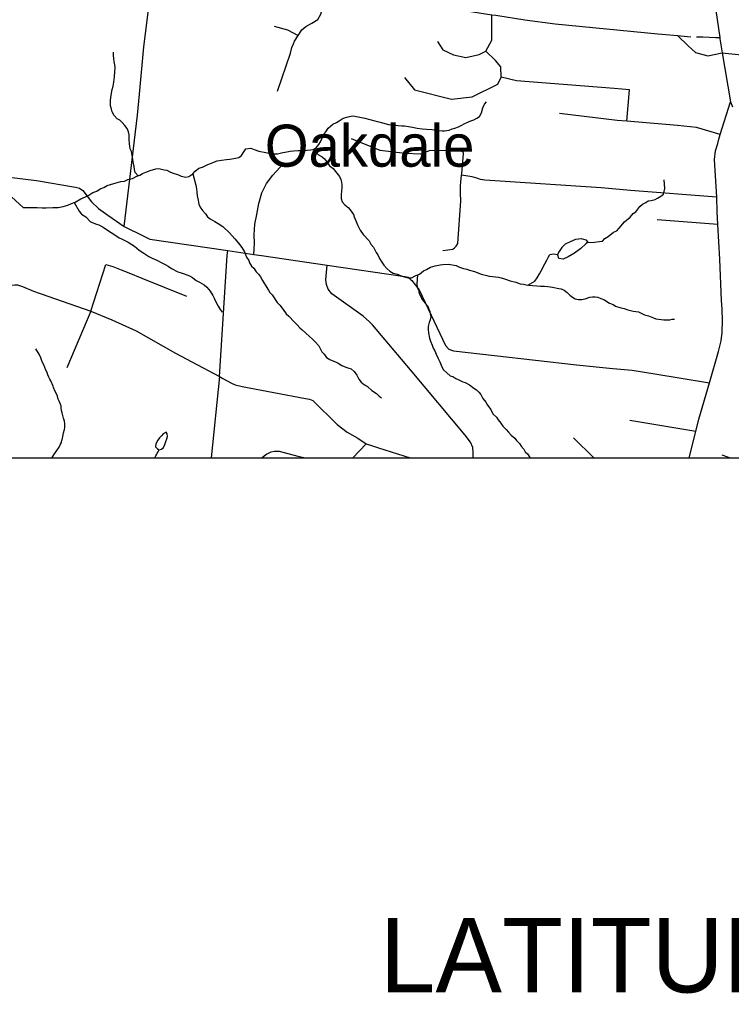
# Model space of a CAD drawing. Extents: x 0 to 34, y 0 to 22.
# Drawn here: x 2.395 to 3.731, y 13.194 to 15.023 of the extents above; entities that cross this region are included whole.
import ezdxf

# ---------------------------------------------------------------- set-up
doc = ezdxf.new("R2010")
doc.units = 0
for name, color, linetype in [('GM_X_County_Road', 7, 'Continuous'), ('GM_X_County_ROW', 7, 'Continuous'), ('GM_X_Minor_Lake', 7, 'Continuous'), ('GM_X_Minor_River', 7, 'Continuous'), ('GM_X_Township_Subdivision', 7, 'Continuous'), ('GM_X_Unincorporated_Text', 7, 'Continuous'), ('SH_Data', 7, 'Continuous')]:
    doc.layers.add(name, color=color, linetype=linetype)

msp = doc.modelspace()

# ---------------------------------------------------------------- linework, layer by layer
at = {"layer": 'GM_X_County_Road'}
for points in [[(2.2258, 15.2235), (2.2987, 15.186), (2.3184, 15.1766), (2.3423, 15.1693), (2.373, 15.1638), (2.4076, 15.1648), (2.4442, 15.1636), (2.6483, 15.131), (2.7856, 15.1056), (2.9731, 15.0809), (3.1585, 15.0511), (3.281, 15.0319), (3.2884, 15.0308), (3.343, 15.0226), (3.3998, 15.0151), (3.5922, 14.9963), (3.5999, 14.9956)], [(2.6198, 14.8825), (2.6281, 14.9717), (2.6483, 15.131)], [(3.6945, 15.0867), (3.7086, 14.9889), (3.7089, 14.9865), (3.7134, 14.9601), (3.7288, 14.8681), (3.7325, 14.8589)], [(3.5999, 14.9956), (3.6295, 14.9929), (3.6491, 14.9734), (3.6629, 14.9607), (3.686, 14.9547), (3.7134, 14.9601)], [(3.6295, 14.9929), (3.6543, 14.9903)], [(3.6768, 14.9901), (3.7006, 14.9892)], [(3.7134, 14.9601), (3.8399, 14.9472), (3.85, 14.9435), (3.9106, 14.9291), (3.9265, 14.9232), (3.9472, 14.9185), (4.0106, 14.9118), (4.0583, 14.9068)], [(3.7129, 14.4789), (3.7118, 14.495), (3.7085, 14.5729), (3.7053, 14.6379), (3.7039, 14.6616), (3.7029, 14.6892), (3.699, 14.7598), (3.7006, 14.7761), (3.7047, 14.7898), (3.7068, 14.7981), (3.7092, 14.807), (3.7288, 14.8681)], [(2.3393, 14.7315), (2.4266, 14.7207), (2.4996, 14.7079), (2.5073, 14.7062), (2.5134, 14.7016), (2.5301, 14.6807), (2.5431, 14.6681), (2.5604, 14.6558), (2.5911, 14.634), (2.6279, 14.6158), (2.6392, 14.6102), (2.7855, 14.589), (2.8343, 14.5818), (2.8491, 14.5796)], [(2.7703, 14.3525), (2.7846, 14.5795), (2.7846, 14.5795)], [(2.7846, 14.5795), (2.7855, 14.589)], [(2.8491, 14.5796), (2.9723, 14.5615), (3.1178, 14.5405), (3.1238, 14.5388), (3.129, 14.5343)], [(2, 14.5396), (2.019, 14.5376), (2.0727, 14.5308), (2.2375, 14.5181), (2.273, 14.5212), (2.3066, 14.52), (2.3558, 14.5219), (2.3858, 14.5244), (2.3884, 14.5247), (2.3912, 14.5244), (2.4003, 14.5218), (2.4213, 14.5128), (2.5283, 14.475), (2.5681, 14.4589), (2.6134, 14.4384), (2.6877, 14.3965), (2.7703, 14.3525)], [(3.129, 14.5343), (3.1309, 14.5326), (3.1449, 14.5152), (3.1617, 14.4795), (3.1943, 14.4106), (3.2005, 14.404), (3.2088, 14.4008), (3.4396, 14.3745), (3.5082, 14.3678), (3.5441, 14.3643), (3.5868, 14.3576), (3.6892, 14.3408)], [(3.6512, 14.2), (3.6635, 14.249), (3.6693, 14.2725), (3.6892, 14.3408), (3.7063, 14.3997), (3.7111, 14.4197), (3.7131, 14.4349), (3.714, 14.4585), (3.7129, 14.4777), (3.7129, 14.4789)], [(2.7703, 14.3525), (2.7763, 14.3485), (2.7925, 14.34), (2.7996, 14.3369), (2.8125, 14.3338), (2.9315, 14.3114), (2.9387, 14.3101), (2.9454, 14.3072), (2.9907, 14.2625), (3.0097, 14.2478), (3.0297, 14.2365), (3.0449, 14.2264), (3.0549, 14.2233), (3.0685, 14.2188), (3.1275, 14.2)]]:
    msp.add_lwpolyline(points, dxfattribs=at)
at = {"layer": 'GM_X_County_ROW'}
for points in [[(3.6649, 14.9905), (3.6768, 14.9901)], [(3.7006, 14.9892), (3.7086, 14.9889)], [(2.5911, 14.634), (2.6162, 14.8432), (2.6198, 14.8825)]]:
    msp.add_lwpolyline(points, dxfattribs=at)
at = {"layer": 'GM_X_Minor_Lake'}
for points in [[(2.657, 14.2147), (2.6612, 14.2158), (2.665, 14.2195), (2.6674, 14.2248), (2.6691, 14.2308), (2.6711, 14.2357), (2.6723, 14.2402), (2.6717, 14.2448), (2.6702, 14.2483), (2.6641, 14.245), (2.661, 14.2412), (2.6575, 14.2371), (2.6543, 14.233), (2.6508, 14.2259), (2.6499, 14.2206)], [(2.6499, 14.2206), (2.6538, 14.2165), (2.657, 14.2147)]]:
    msp.add_lwpolyline(points, dxfattribs=at)
at = {"layer": 'GM_X_Minor_River'}
for points in [[(2.6176, 14.7296), (2.6118, 14.7354), (2.6108, 14.7411), (2.6098, 14.7472), (2.6088, 14.7526), (2.6075, 14.7598), (2.6062, 14.7679), (2.6049, 14.7751), (2.6027, 14.7802), (2.6017, 14.7848), (2.6011, 14.7897), (2.6006, 14.7981), (2.6004, 14.8065), (2.5994, 14.8119), (2.5965, 14.8184), (2.5925, 14.8239), (2.5873, 14.8297), (2.5829, 14.8336), (2.578, 14.8361), (2.5721, 14.8427), (2.5685, 14.8493), (2.5671, 14.8546), (2.5657, 14.8608), (2.5655, 14.8654), (2.5653, 14.8707), (2.5662, 14.8764), (2.5675, 14.8843), (2.5689, 14.8915), (2.5705, 14.8976), (2.5719, 14.9055), (2.5733, 14.915), (2.5739, 14.9245), (2.5741, 14.9321), (2.5735, 14.9375), (2.5722, 14.944), (2.5716, 14.9493), (2.5714, 14.9562), (2.5711, 14.9615)], [(3.1411, 14.8188), (3.1502, 14.8178), (3.1586, 14.8168), (3.1681, 14.8161), (3.173, 14.8156), (3.1821, 14.8142), (3.1878, 14.8137), (3.1923, 14.8139), (3.2007, 14.8152), (3.2065, 14.8174), (3.2115, 14.8187), (3.2184, 14.8216), (3.2246, 14.8245), (3.2292, 14.827), (3.2369, 14.831), (3.2415, 14.8324), (3.2469, 14.8345), (3.2527, 14.8374), (3.2577, 14.8407), (3.2617, 14.8474), (3.2642, 14.8572), (3.2675, 14.864), (3.271, 14.8685)], [(2.3576, 14.7092), (2.4016, 14.6696), (2.4138, 14.6697), (2.4218, 14.6702), (2.4279, 14.67), (2.437, 14.6694), (2.4446, 14.6692), (2.4571, 14.6696), (2.4674, 14.6701), (2.4766, 14.6721), (2.4854, 14.6741), (2.4923, 14.6774), (2.4989, 14.6799), (2.5097, 14.6864), (2.5185, 14.69), (2.5247, 14.6929), (2.5324, 14.698), (2.5397, 14.7004), (2.5463, 14.7052), (2.5532, 14.7077), (2.5594, 14.7113), (2.5652, 14.7134), (2.5763, 14.7162), (2.5851, 14.7186), (2.5916, 14.7192), (2.5981, 14.7224), (2.6065, 14.7245), (2.6147, 14.7288), (2.6208, 14.7305), (2.6254, 14.7338), (2.635, 14.7374), (2.64, 14.7391), (2.6504, 14.7423), (2.6561, 14.7429), (2.6663, 14.7407), (2.6712, 14.7398), (2.6769, 14.737), (2.6814, 14.7353), (2.6934, 14.7312), (2.6979, 14.7288), (2.707, 14.7266), (2.7124, 14.7283), (2.7201, 14.7331), (2.7244, 14.7383), (2.7314, 14.7438), (2.7379, 14.7459), (2.7483, 14.7506), (2.7549, 14.7534), (2.7606, 14.7556), (2.7656, 14.7573), (2.774, 14.7586), (2.7832, 14.7599), (2.7893, 14.7605), (2.797, 14.7622), (2.8061, 14.7638), (2.8112, 14.7675), (2.8155, 14.7742), (2.8195, 14.7798), (2.829, 14.7814), (2.8351, 14.779), (2.8437, 14.7757), (2.857, 14.773), (2.863, 14.7717), (2.8694, 14.7708), (2.8786, 14.7709), (2.8889, 14.7729), (2.8965, 14.7742), (2.9023, 14.776), (2.9088, 14.7766), (2.9179, 14.7771), (2.9285, 14.7768), (2.9343, 14.7774), (2.9408, 14.7779), (2.9457, 14.7786), (2.9515, 14.7818), (2.9566, 14.7882), (2.9594, 14.7934), (2.9622, 14.799), (2.9655, 14.8073), (2.9694, 14.8118), (2.9738, 14.8189), (2.9824, 14.8263), (2.9897, 14.8295), (2.9947, 14.8328), (3.0021, 14.8379), (3.0117, 14.8403), (3.0189, 14.842), (3.0239, 14.8415), (3.0333, 14.8397), (3.0424, 14.8379), (3.0522, 14.835), (3.0616, 14.8328), (3.0662, 14.8316), (3.076, 14.8286), (3.0869, 14.8256), (3.0964, 14.825), (3.1055, 14.824), (3.1124, 14.8234), (3.1173, 14.8233), (3.132, 14.8206), (3.1411, 14.8188)], [(2.946, 14.7767), (2.9505, 14.7739), (2.9557, 14.7691), (2.9624, 14.7648), (2.9669, 14.7616), (2.9706, 14.7562), (2.9764, 14.748), (2.9835, 14.7432), (2.9879, 14.7374), (2.9953, 14.7281), (2.9978, 14.7227), (2.9992, 14.7173), (2.9994, 14.7127), (2.9993, 14.7066), (2.9988, 14.7021), (2.9982, 14.6929), (2.998, 14.6869), (3.0001, 14.6807), (3.0049, 14.6749), (3.0112, 14.6701), (3.0149, 14.6654), (3.0215, 14.6569), (3.0225, 14.6523), (3.0265, 14.6434), (3.029, 14.6373), (3.0337, 14.6276), (3.0395, 14.6191), (3.0506, 14.6073), (3.0542, 14.6011), (3.059, 14.5953), (3.0616, 14.5907), (3.0641, 14.5856), (3.067, 14.581), (3.0702, 14.5744), (3.0731, 14.569), (3.0783, 14.5616), (3.0838, 14.5554), (3.0898, 14.5506), (3.0961, 14.5467), (3.1037, 14.5445), (3.1123, 14.5409), (3.124, 14.5379), (3.1305, 14.5381), (3.1386, 14.5424), (3.1451, 14.5445), (3.1525, 14.5512), (3.1587, 14.5533), (3.166, 14.558), (3.1748, 14.5601), (3.184, 14.5621), (3.1893, 14.5627), (3.1996, 14.5632), (3.214, 14.5609), (3.2204, 14.558), (3.2279, 14.5552), (3.2343, 14.5538), (3.2389, 14.5522), (3.2483, 14.5496), (3.2532, 14.5476), (3.2607, 14.5447), (3.2717, 14.5425), (3.2762, 14.5412), (3.2823, 14.5403), (3.2933, 14.5389), (3.2982, 14.538), (3.3069, 14.5354), (3.3152, 14.5325), (3.3261, 14.53), (3.3344, 14.5267), (3.3401, 14.5261), (3.3454, 14.5245), (3.3499, 14.524), (3.3575, 14.5234), (3.3651, 14.5228), (3.3723, 14.5222), (3.3799, 14.5224), (3.386, 14.5218), (3.3905, 14.5209), (3.3951, 14.5204), (3.4064, 14.5178), (3.4113, 14.5169), (3.417, 14.5145), (3.4222, 14.5101), (3.4274, 14.5054), (3.4322, 14.5015), (3.4374, 14.4983), (3.4435, 14.4974), (3.4496, 14.4972), (3.4561, 14.4985), (3.4649, 14.5017), (3.4699, 14.5023), (3.4748, 14.5022), (3.4801, 14.5013), (3.4854, 14.4989), (3.4922, 14.4964), (3.4966, 14.4936), (3.5015, 14.4904), (3.5086, 14.4875), (3.5131, 14.4848), (3.5214, 14.4819), (3.5294, 14.4801)], [(2.72, 14.733), (2.7256, 14.7116), (2.7266, 14.7047), (2.7272, 14.6986), (2.7281, 14.6917), (2.7302, 14.6837), (2.7315, 14.6764), (2.7336, 14.6703), (2.7384, 14.664), (2.7439, 14.6578), (2.7472, 14.6524), (2.7528, 14.6488), (2.761, 14.6436), (2.7674, 14.6396), (2.776, 14.634), (2.789, 14.6223), (2.7938, 14.6168), (2.7989, 14.6109), (2.8059, 14.6027), (2.8118, 14.595), (2.8169, 14.5864), (2.8205, 14.5768), (2.8248, 14.5706), (2.8266, 14.566), (2.8299, 14.5598), (2.8343, 14.5563), (2.8387, 14.5489), (2.8432, 14.545), (2.8468, 14.5395), (2.8508, 14.533), (2.8545, 14.5264), (2.8617, 14.5147), (2.8643, 14.5101), (2.8691, 14.5058), (2.8779, 14.4918), (2.8834, 14.4863), (2.8897, 14.4786), (2.8952, 14.4704), (2.9004, 14.4661), (2.91, 14.4551), (2.9155, 14.4497), (2.9207, 14.4442), (2.9251, 14.4399), (2.9385, 14.4281), (2.9452, 14.4218), (2.9496, 14.4175), (2.9563, 14.4101), (2.9621, 14.3989), (2.9661, 14.3942), (2.9705, 14.3883), (2.9773, 14.3844), (2.9825, 14.3819), (2.9878, 14.3799), (2.9927, 14.3774), (2.9994, 14.3731), (3.0069, 14.3698), (3.0126, 14.3681), (3.0171, 14.3669), (3.0227, 14.3618), (3.0278, 14.3548), (3.0314, 14.3474), (3.0358, 14.342), (3.0418, 14.3372), (3.0478, 14.3336), (3.0559, 14.3262), (3.0645, 14.3206), (3.0697, 14.3159), (3.0742, 14.3127)], [(3.4608, 14.6044), (3.4733, 14.6045), (3.4832, 14.6059), (3.4887, 14.6069), (3.493, 14.6117), (3.4992, 14.6154), (3.5093, 14.6238), (3.5154, 14.6263), (3.5201, 14.6308), (3.5296, 14.6431), (3.5405, 14.6519), (3.546, 14.6586), (3.551, 14.6615), (3.5589, 14.672), (3.5639, 14.676), (3.5697, 14.6793), (3.5744, 14.6822), (3.5801, 14.6832), (3.5874, 14.6852), (3.592, 14.6874), (3.5982, 14.6914), (3.6029, 14.6951), (3.6054, 14.7057), (3.6044, 14.7221)], [(2.4976, 14.6794), (2.5068, 14.6629), (2.5112, 14.6571), (2.519, 14.6523), (2.5279, 14.6433), (2.5392, 14.6384), (2.5437, 14.6371), (2.552, 14.6327), (2.562, 14.6259), (2.5718, 14.6196), (2.5815, 14.6128), (2.586, 14.6112), (2.5987, 14.6047), (2.6055, 14.6007), (2.6103, 14.5975), (2.6193, 14.5901), (2.6278, 14.5841), (2.6376, 14.5777), (2.6436, 14.5745), (2.6522, 14.5712), (2.662, 14.566), (2.6691, 14.562), (2.6736, 14.5596), (2.6799, 14.5556), (2.6919, 14.5492), (2.6965, 14.5479), (2.7036, 14.5451), (2.7138, 14.5413), (2.7194, 14.5385), (2.7261, 14.5326), (2.7325, 14.5294), (2.7411, 14.5246), (2.7463, 14.5203), (2.7522, 14.5125), (2.7573, 14.5047), (2.7605, 14.4985), (2.763, 14.4928), (2.7678, 14.4846), (2.7714, 14.4781), (2.7749, 14.4732)], [(3.4125, 14.5946), (3.4195, 14.6015), (3.4283, 14.6063), (3.4383, 14.6106), (3.4485, 14.6119), (3.4572, 14.6094), (3.4609, 14.6048), (3.4574, 14.6014), (3.4481, 14.5929), (3.4362, 14.5844), (3.4242, 14.5771), (3.415, 14.5731), (3.4067, 14.5741), (3.4046, 14.5806), (3.4044, 14.5819)], [(3.3486, 14.5241), (3.3615, 14.5313), (3.3659, 14.5376), (3.3706, 14.5451), (3.3738, 14.5507), (3.3803, 14.5642), (3.3843, 14.571), (3.3871, 14.577), (3.3899, 14.5819), (3.3976, 14.5826), (3.4044, 14.5816)], [(3.4125, 14.5946), (3.4071, 14.5873), (3.4044, 14.5819)], [(3.1416, 14.5434), (3.1404, 14.5268), (3.141, 14.5199), (3.1432, 14.5153), (3.1449, 14.5087), (3.1478, 14.503), (3.1499, 14.4979), (3.1562, 14.4905), (3.1606, 14.4847), (3.1627, 14.4793), (3.1645, 14.4747), (3.1655, 14.4701), (3.1665, 14.4647), (3.1652, 14.4587), (3.1636, 14.4542), (3.1618, 14.4462), (3.1613, 14.4409), (3.1619, 14.4344), (3.1639, 14.4244), (3.1657, 14.4187), (3.1693, 14.4114), (3.171, 14.4056), (3.1743, 14.4009), (3.1768, 14.3944), (3.18, 14.3863), (3.1836, 14.3801), (3.1872, 14.3709), (3.1905, 14.3651), (3.1964, 14.3596), (3.2027, 14.3537), (3.2076, 14.3524), (3.2132, 14.3488), (3.2177, 14.3472), (3.2264, 14.3427), (3.2309, 14.3415), (3.2391, 14.3371), (3.2473, 14.3304), (3.2522, 14.3276), (3.2566, 14.3232), (3.2603, 14.3186), (3.2639, 14.3112), (3.2698, 14.3042), (3.2727, 14.2988), (3.2789, 14.2903), (3.2829, 14.2825), (3.2896, 14.2763), (3.2929, 14.2712), (3.298, 14.265), (3.3017, 14.2595), (3.308, 14.2533), (3.3124, 14.2478), (3.3172, 14.2427), (3.3239, 14.2368), (3.3272, 14.2322), (3.3331, 14.2267), (3.3357, 14.222), (3.3408, 14.2162), (3.3437, 14.2112), (3.3482, 14.2072), (3.3522, 14.2003), (3.3525, 14.2)], [(3.5294, 14.4801), (3.5361, 14.4776), (3.546, 14.4755), (3.5562, 14.4737), (3.5675, 14.4684), (3.575, 14.4667), (3.5844, 14.463), (3.5889, 14.4609), (3.5935, 14.46), (3.5988, 14.4595), (3.6037, 14.459), (3.609, 14.4589), (3.6147, 14.4591), (3.6193, 14.4605), (3.6238, 14.4601)], [(2.4557, 14.2), (2.4558, 14.2002), (2.4606, 14.2073), (2.465, 14.2136), (2.4689, 14.22), (2.4717, 14.2256), (2.4733, 14.2286), (2.4734, 14.2309), (2.4746, 14.2339), (2.4759, 14.2396), (2.4773, 14.2468), (2.4789, 14.2528), (2.4798, 14.2566), (2.48, 14.2635), (2.479, 14.2688), (2.4772, 14.2746), (2.4759, 14.2796), (2.4748, 14.2842), (2.4738, 14.2884), (2.4732, 14.2937), (2.4729, 14.2968), (2.4708, 14.3018), (2.4693, 14.306), (2.4676, 14.3103), (2.4658, 14.3156), (2.464, 14.3199), (2.4619, 14.3241), (2.4586, 14.3318), (2.4579, 14.3341), (2.4533, 14.3442), (2.4515, 14.3476), (2.45, 14.3511), (2.4479, 14.3557), (2.4465, 14.36), (2.4443, 14.3642), (2.4425, 14.3692), (2.4404, 14.3742), (2.4382, 14.3788), (2.4361, 14.3839), (2.4347, 14.3873), (2.4314, 14.3943), (2.4296, 14.3977), (2.4274, 14.4012), (2.4256, 14.4047)], [(2.6489, 14.2), (2.6506, 14.2035), (2.6522, 14.2065), (2.6531, 14.2087), (2.655, 14.2114), (2.657, 14.2147)]]:
    msp.add_lwpolyline(points, dxfattribs=at)
at = {"layer": 'GM_X_Township_Subdivision'}
for points in [[(2.8788, 14.8884), (2.903, 14.9595), (2.906, 14.9705), (2.9086, 14.9773), (2.9106, 14.9824), (2.9175, 14.9927), (2.9243, 15.0038), (2.9323, 15.0098), (2.9433, 15.0159), (2.9542, 15.0232), (2.96, 15.0328), (2.9638, 15.0458), (2.9731, 15.0809)], [(3.1791, 14.9817), (3.1891, 14.9662), (3.2089, 14.9569), (3.2321, 14.9514), (3.2569, 14.9574), (3.2696, 14.9635), (3.2812, 14.9844), (3.2812, 15.0159), (3.281, 15.0319)], [(2.8724, 15.0102), (2.8973, 15.0035), (2.9175, 14.9927)], [(3.1174, 14.9138), (3.1361, 14.8907), (3.2056, 14.8736), (3.2442, 14.878), (3.2922, 14.9017), (3.2983, 14.9149), (3.2977, 14.9343), (3.2878, 14.9458), (3.2696, 14.9635)], [(3.5104, 14.8933), (3.3275, 14.9078), (3.2983, 14.9149)], [(3.5395, 14.891), (3.5104, 14.8933)], [(3.534, 14.8318), (3.5395, 14.891)], [(3.7092, 14.807), (3.6647, 14.8203), (3.6296, 14.8239), (3.534, 14.8318), (3.5161, 14.8334), (3.4079, 14.8466)], [(3.2244, 14.733), (3.228, 14.7716), (3.2278, 14.7727), (3.2271, 14.7736), (3.225, 14.7749), (3.2209, 14.7761), (3.1654, 14.777), (3.1471, 14.7699), (3.1179, 14.771), (3.0716, 14.7771), (3.0175, 14.7986)], [(2.8343, 14.5818), (2.8356, 14.603), (2.8348, 14.6186), (2.8364, 14.6383), (2.8403, 14.6568), (2.8439, 14.6776), (2.8497, 14.6976), (2.8585, 14.7149), (2.8703, 14.7309), (2.8902, 14.7524)], [(3.1888, 14.5889), (3.2075, 14.5915), (3.211, 14.594), (3.2141, 14.5974), (3.2169, 14.6022), (3.2227, 14.6826), (3.2219, 14.6967), (3.2223, 14.7111), (3.2229, 14.7176), (3.2241, 14.7304), (3.2244, 14.733)], [(3.2639, 14.7218), (3.2635, 14.7219), (3.2594, 14.7223), (3.253, 14.7252), (3.2439, 14.7277), (3.2241, 14.7304)], [(3.7029, 14.6892), (3.5414, 14.7019), (3.4859, 14.707), (3.2677, 14.7214), (3.2639, 14.7218)], [(3.7053, 14.6379), (3.5914, 14.6467)], [(2.5283, 14.475), (2.5569, 14.5629), (2.5701, 14.5592), (2.5853, 14.5531), (2.6001, 14.5473), (2.6241, 14.5371), (2.7084, 14.5037)], [(3.2459, 14.2), (3.2461, 14.2096), (3.2452, 14.2195), (3.2409, 14.2291), (3.231, 14.2426), (3.1286, 14.3648), (3.0571, 14.4494), (3.0512, 14.4552), (3.0393, 14.4658), (2.9808, 14.5078), (2.9742, 14.5164), (2.971, 14.5252), (2.9697, 14.5339), (2.9723, 14.5615)], [(2.5283, 14.475), (2.4837, 14.3691)], [(2.7703, 14.3525), (2.7545, 14.2)], [(3.6635, 14.249), (3.5396, 14.27)], [(3.4723, 14.2), (3.4339, 14.2376)], [(3.0449, 14.2264), (3.0201, 14.2)], [(2.9282, 14.2), (2.9179, 14.2021), (2.8823, 14.2115), (2.8735, 14.2115), (2.8665, 14.2103), (2.8591, 14.2069), (2.8536, 14.2031), (2.8501, 14.2)], [(3.7266, 14.2), (3.7238, 14.2009), (3.713, 14.2047)]]:
    msp.add_lwpolyline(points, dxfattribs=at)
at = {"layer": 'SH_Data'}
msp.add_line((2, 14.2), (8.8, 14.2), dxfattribs=at)

# ---------------------------------------------------------------- texts
at = {"layer": 'GM_X_Unincorporated_Text'}
msp.add_text('Oakdale', height=0.07898, rotation=0, dxfattribs=at).set_placement((2.855, 14.7465))
at = {"layer": 'SH_Data'}
msp.add_text('LATITUDE:  39° 16\' 12"     LONGITUDE:  -84° 34\' 26"', height=0.14, dxfattribs=at).set_placement((3.071, 13.1959))

doc.saveas('drawing.dxf')
